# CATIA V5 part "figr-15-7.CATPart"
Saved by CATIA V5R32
Part number: Part1
Bounding box of the stored display mesh (mm): x -50 to 50, y -32.5 to 33.5, z -52 to 1
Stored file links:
  D:\PROJECTS\Project 2022\CATIA V5 6R 2022\Resources\Part Files\c15_catia_v5_6r2022_prt\figr-15-7.CATPart
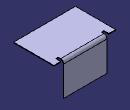
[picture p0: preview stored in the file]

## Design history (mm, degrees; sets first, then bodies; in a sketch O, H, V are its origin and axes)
SheetMetalParameters1: Thickness 1, BendRadius 4, KFactor 0.475772 {= log(min(100,max(20*SheetMetalParameters1.BendRadius,SheetMetalParameters1.Thickness)/SheetMetalParameters1.Thickness))/log(100)/2}, ReliefRadialLength 4, ReliefAxialLength 4, MinimumBendRadius 0
Body1 (main body)
  Sketch1 on xy-plane, origin (0, 0, 0), H (1, 0, 0), V (0, 1, 0)
    line L1 (-50, 32.5) -> (50, 32.5)
    line L2 (50, 32.5) -> (50, -32.5)
    line L3 (50, -32.5) -> (-50, -32.5)
    line L4 (-50, -32.5) -> (-50, 32.5)
    length L1 = 100
    length L2 = 65
    horizontal: L1 H, L3 H
    vertical: L2 V, L4 V
    symmetry: L4 L2 V, L1 L3 H
  Wall1: Thickness 1, Profile Sketch1
  d_NewWallOnEdge1: NewWallOnEdge_Edge edge [face of Wall1 | face of Wall1], NewWallOnEdge_Length 53, NewWallOnEdge_HeightLimitOffset 0, NewWallOnEdge_WidthOffset1 -15, NewWallOnEdge_WidthOffset2 -15, NewWallOnEdge_Angle 90, NewWallOnEdge_BendRadiusValue 4 {= SheetMetalParameters1.BendRadius}, NewWallOnEdge_BendTable SheetMetalParameters1, KFacteur 0.475772 {= log(min(100,max(20*d_NewWallOnEdge1.Radius,SheetMetalParameters1.Thickness)/SheetMetalParameters1.Thickness))/log(100)/2}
